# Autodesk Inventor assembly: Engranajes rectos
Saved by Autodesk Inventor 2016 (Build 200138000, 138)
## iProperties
Created: 2016-06
Part Number: Engranajes rectos
Document SubType Name: Assembly
Designer: adm
Categories: <?xml version="1.0" encoding="UTF-16"?> <MemberInstance><Categories><FamilyTemplate/><ParamToTemplateMap><ParamToTemplate><ParamToTemplate CategoryParameter="//
ClientObjectVersion: 1
Author: adm
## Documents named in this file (3)
- C:\Users\adm\Desktop\recepcion 2\158\Design Accelerator\Engranajes rectos1.iam
- C:\Users\adm\Desktop\recepcion 2\158\Design Accelerator\Engranaje recto11.ipt
- C:\Users\adm\Desktop\recepcion 2\158\Design Accelerator\Engranaje recto21.ipt
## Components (2 placed, 2 different names)
1. Engranaje recto1:1 — Rotación:1
2. Engranaje recto2:1 — Rotación:1
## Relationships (1: RelateRotation 1)
- Rotación:1 [RelateRotation]: Engranaje recto1:1 ↔ Engranaje recto2:1
